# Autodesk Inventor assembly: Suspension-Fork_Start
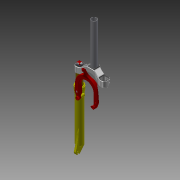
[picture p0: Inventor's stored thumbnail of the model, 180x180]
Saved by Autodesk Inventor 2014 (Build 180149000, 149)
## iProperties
Shininess: 64.0
Length Units: 11272
Angle Units: 11279
Time Units: 11290
Mass Units: 11286
Length Display Precision: 3
Angle Display Precision: 2
Compacted: True
Created: 2001-11
Part Number: Suspension-Fork_Start
Document SubType Name: Assembly
Designer: Autodesk, Inc.
Mass: 432.707 g
Surface Area: 2527.99 cm^2
Volume: 429.637 cm^3
Density: 1.00715 g/cm^3
Density: 0.0
Volumn: 0.0
Area: 0.0
PropertySet Name: Model Information
Control State: 0
Master: False
Checked Out: False
Author: Autodesk, Inc.
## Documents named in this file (11)
- C:\Users\iTools\Desktop\tutorial files\Assembly FEA 3\Suspension-Fork_Start.iam
- C:\Users\iTools\Desktop\tutorial files\Assembly FEA 3\Components\Dial-Elastomer.iam
- C:\Users\iTools\Desktop\tutorial files\Assembly FEA 3\Components\Head Tube.ipt
- C:\Users\iTools\Desktop\tutorial files\Assembly FEA 3\Components\Fork-Slider.ipt
- C:\Users\iTools\Desktop\tutorial files\Assembly FEA 3\Components\Fork-Piston.ipt
- C:\Users\iTools\Desktop\tutorial files\Assembly FEA 3\Components\Fork-Crown.ipt
- C:\Users\iTools\Desktop\tutorial files\Assembly FEA 3\Components\Fork-Brace.ipt
- C:\Users\iTools\Desktop\tutorial files\Assembly FEA 3\Components\Fork-Tube.ipt
- C:\Users\iTools\Desktop\tutorial files\Assembly FEA 3\Components\Fork-Damper.ipt
- C:\Users\iTools\Desktop\tutorial files\Assembly FEA 3\Standard Parts\UNI 5933 - M4 x 12.ipt
- C:\Users\iTools\Desktop\tutorial files\Assembly FEA 3\Standard Parts\NF E 25-125 - M3 x 10.ipt
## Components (11 placed, 10 different names)
1. Fork-Crown:1 — Mate:7, Tangent:1, Angle:1, Mate:10, Insert:15, Mate:11, Insert:20, Insert:21
2. Head Tube:1 — Mate:7, Tangent:1
3. Fork-Brace:1 — Insert:22
4. Dial-Elastomer [sub-assembly] — Insert:19
5. Fork-Slider:1 — Insert:2, Angle:1, Mate:10, Mate:11
6. Fork-Piston:1 — Insert:2
7. UNI 5933 M4 x 12:1 — Insert:22
8. NF E 25-125 M3 x 10:1 — Insert:20
9. NF E 25-125 M3 x 10:2 — Insert:21
10. Fork-Tube:1 — Insert:15, Insert:16, Insert:19
11. Fork-Damper:1 — Insert:16
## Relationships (12: Insert 7, Mate 3, Tangent 1, Angle 1)
- Insert:2: Fork-Slider:1 ↔ Fork-Piston:1
- Mate:7: Fork-Crown:1 ↔ Head Tube:1
- Tangent:1: Fork-Crown:1 ↔ Head Tube:1
- Angle:1: Fork-Crown:1 ↔ Fork-Slider:1
- Mate:10: Fork-Crown:1 ↔ Fork-Slider:1
- Insert:15: Fork-Crown:1 ↔ Fork-Tube:1
- Insert:16: Fork-Tube:1 ↔ Fork-Damper:1
- Mate:11: Fork-Crown:1 ↔ Fork-Slider:1
- Insert:19: Dial-Elastomer ↔ Fork-Tube:1
- Insert:20: Fork-Crown:1 ↔ NF E 25-125 M3 x 10:1
- Insert:21: Fork-Crown:1 ↔ NF E 25-125 M3 x 10:2
- Insert:22: Fork-Brace:1 ↔ UNI 5933 M4 x 12:1
